// Mitsubishi GX Works2 project: Q系列PLC与BD4543V4241E通信例程   PLC: Q02/Q02H

PROGRAM MAIN
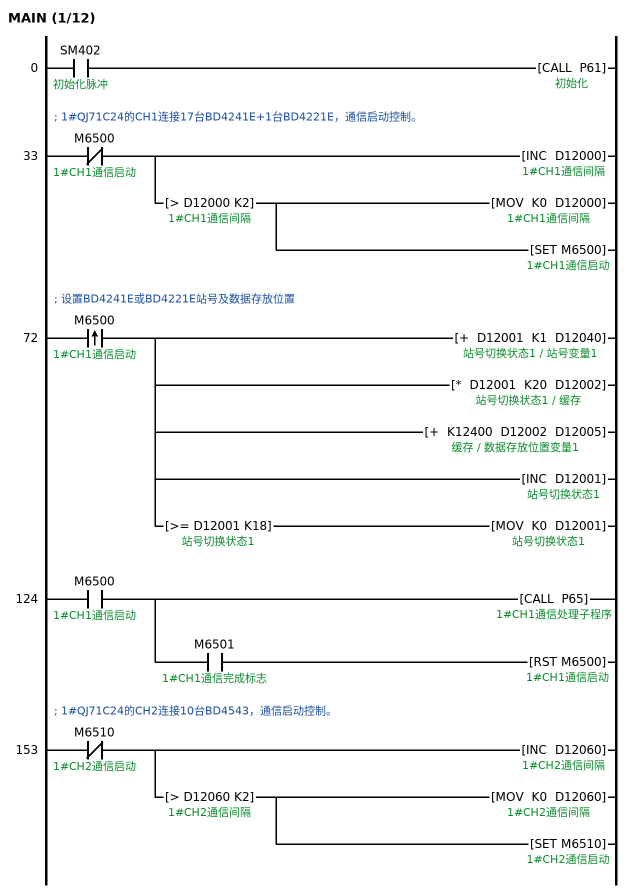
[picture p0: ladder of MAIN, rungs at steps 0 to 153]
0     LD      SM402  ; 初始化脉冲
      CALL    P61  ; 初始化
; 1#QJ71C24的CH1连接17台BD4241E+1台BD4221E，通信启动控制。
33    LDI     M6500  ; 1#CH1通信启动
      INC     D12000  ; 1#CH1通信间隔
      AND>    D12000 K2  ; 1#CH1通信间隔
      MOV     K0 D12000
      SET     M6500  ; 1#CH1通信启动
; 设置BD4241E或BD4221E站号及数据存放位置
72    LDP     M6500  ; 1#CH1通信启动
      +       D12001 K1 D12040  ; 站号切换状态1 / 站号变量1
        [note] 参与通讯站号
      *       D12001 K20 D12002  ; 缓存
      +       K12400 D12002 D12005  ; 数据存放位置变量1
        [note] 数据存放开始位置（D号）
      INC     D12001
      AND>=   D12001 K18  ; 站号切换状态1
      MOV     K0 D12001
        [note] BD4241/21模块个数
124   LD      M6500  ; 1#CH1通信启动
      CALL    P65  ; 1#CH1通信处理子程序
      AND     M6501  ; 1#CH1通信完成标志
      RST     M6500  ; 1#CH1通信启动
; 1#QJ71C24的CH2连接10台BD4543，通信启动控制。
153   LDI     M6510  ; 1#CH2通信启动
      INC     D12060  ; 1#CH2通信间隔
      AND>    D12060 K2  ; 1#CH2通信间隔
      MOV     K0 D12060
      SET     M6510  ; 1#CH2通信启动
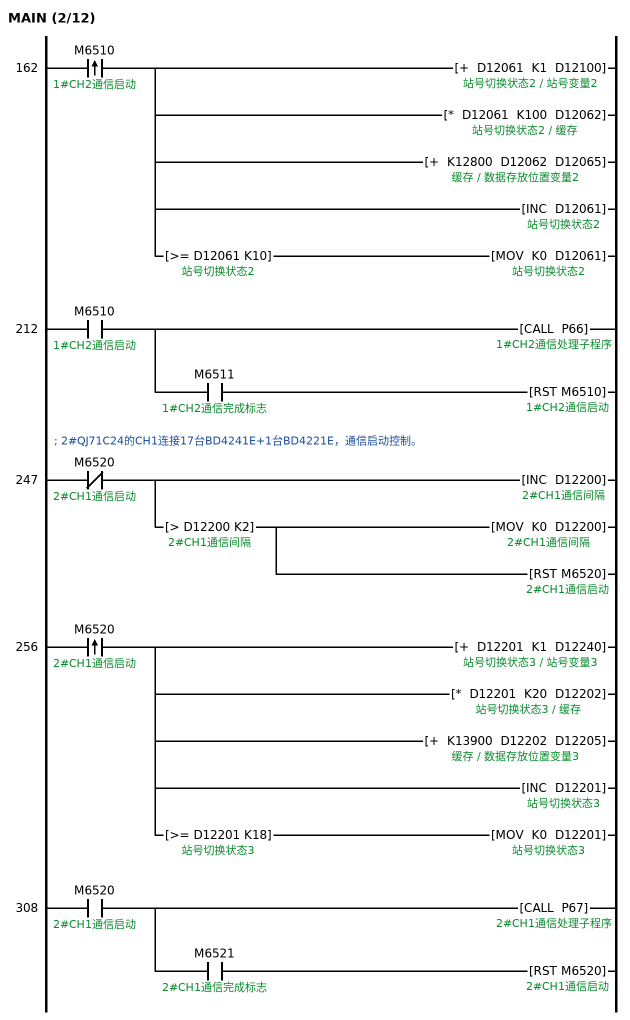
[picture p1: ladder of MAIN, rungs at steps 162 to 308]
162   LDP     M6510  ; 1#CH2通信启动
      +       D12061 K1 D12100  ; 站号切换状态2 / 站号变量2
        [note] 参与通讯站号
      *       D12061 K100 D12062  ; 缓存
      +       K12800 D12062 D12065  ; 数据存放位置变量2
        [note] 数据存放开始位置（D号）
      INC     D12061
      AND>=   D12061 K10  ; 站号切换状态2
      MOV     K0 D12061
        [note] BD4543模块个数
212   LD      M6510  ; 1#CH2通信启动
      CALL    P66  ; 1#CH2通信处理子程序
      AND     M6511  ; 1#CH2通信完成标志
      RST     M6510  ; 1#CH2通信启动
; 2#QJ71C24的CH1连接17台BD4241E+1台BD4221E，通信启动控制。
247   LDI     M6520  ; 2#CH1通信启动
      INC     D12200  ; 2#CH1通信间隔
      AND>    D12200 K2  ; 2#CH1通信间隔
      MOV     K0 D12200
      RST     M6520  ; 2#CH1通信启动
256   LDP     M6520  ; 2#CH1通信启动
      +       D12201 K1 D12240  ; 站号切换状态3 / 站号变量3
        [note] 参与通讯站号
      *       D12201 K20 D12202  ; 缓存
      +       K13900 D12202 D12205  ; 数据存放位置变量3
        [note] 数据存放开始位置（D号）
      INC     D12201
      AND>=   D12201 K18  ; 站号切换状态3
      MOV     K0 D12201
        [note] BD4241/21模块个数
308   LD      M6520  ; 2#CH1通信启动
      CALL    P67  ; 2#CH1通信处理子程序
      AND     M6521  ; 2#CH1通信完成标志
      RST     M6520  ; 2#CH1通信启动
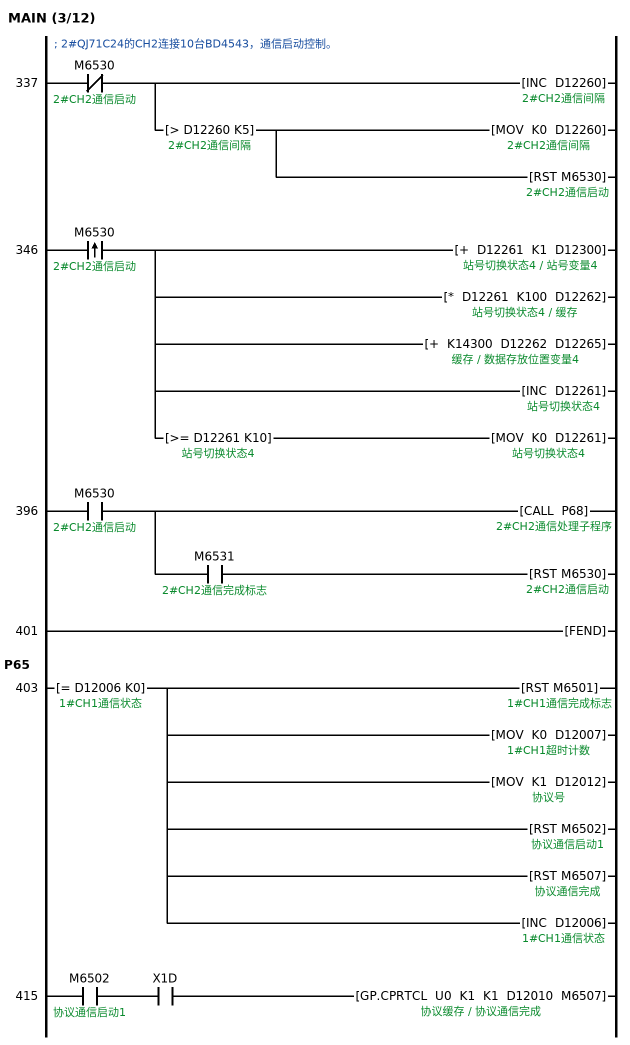
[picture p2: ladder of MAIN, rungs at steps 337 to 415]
; 2#QJ71C24的CH2连接10台BD4543，通信启动控制。
337   LDI     M6530  ; 2#CH2通信启动
      INC     D12260  ; 2#CH2通信间隔
      AND>    D12260 K5  ; 2#CH2通信间隔
      MOV     K0 D12260
      RST     M6530  ; 2#CH2通信启动
346   LDP     M6530  ; 2#CH2通信启动
      +       D12261 K1 D12300  ; 站号切换状态4 / 站号变量4
        [note] 参与通讯站号
      *       D12261 K100 D12262  ; 缓存
      +       K14300 D12262 D12265  ; 数据存放位置变量4
        [note] 数据存放开始位置（D号）
      INC     D12261
      AND>=   D12261 K10  ; 站号切换状态4
      MOV     K0 D12261
        [note] BD4543模块个数
396   LD      M6530  ; 2#CH2通信启动
      CALL    P68  ; 2#CH2通信处理子程序
      AND     M6531  ; 2#CH2通信完成标志
      RST     M6530  ; 2#CH2通信启动
401   FEND
      P65
403   LD=     D12006 K0  ; 1#CH1通信状态
      RST     M6501  ; 1#CH1通信完成标志
      MOV     K0 D12007  ; 1#CH1超时计数
      MOV     K1 D12012  ; 协议号
      RST     M6502  ; 协议通信启动1
      RST     M6507  ; 协议通信完成
      INC     D12006
415   LD      M6502  ; 协议通信启动1
      AND     X1D
      GP.CPRTCL U0 K1 K1 D12010 M6507  ; 协议缓存
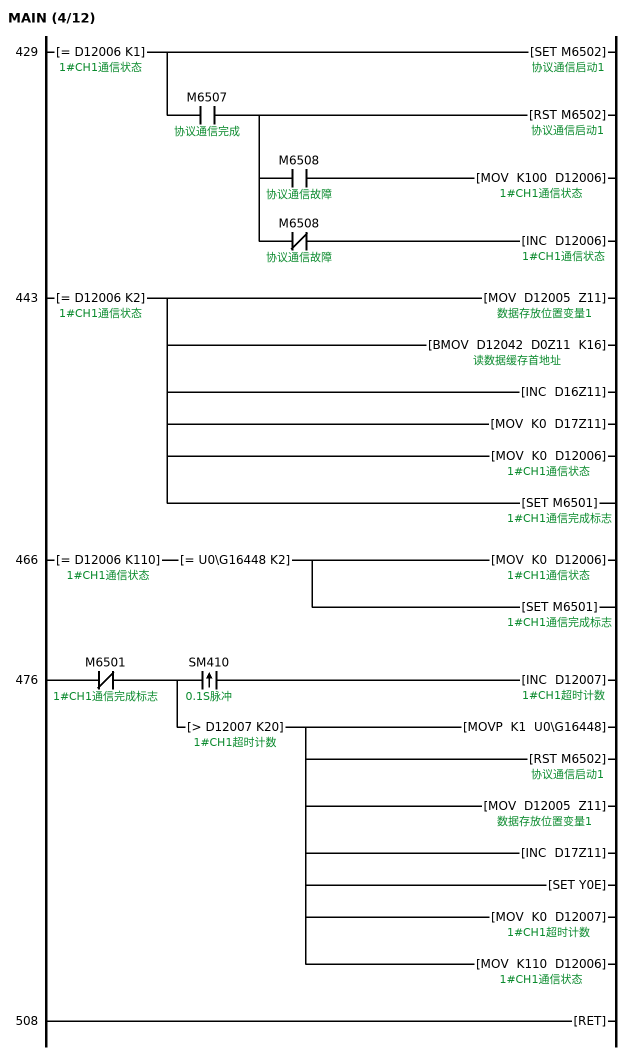
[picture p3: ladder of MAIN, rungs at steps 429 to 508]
429   LD=     D12006 K1  ; 1#CH1通信状态
      SET     M6502  ; 协议通信启动1
      AND     M6507  ; 协议通信完成
      RST     M6502  ; 协议通信启动1
      MPS
      AND     M6508  ; 协议通信故障
      MOV     K100 D12006
      MPP
      ANI     M6508  ; 协议通信故障
      INC     D12006
443   LD=     D12006 K2  ; 1#CH1通信状态
      MOV     D12005 Z11
      BMOV    D12042 D0Z11 K16  ; 读数据缓存首地址
      INC     D16Z11
        [note] 通信计数
      MOV     K0 D17Z11
      MOV     K0 D12006
      SET     M6501  ; 1#CH1通信完成标志
466   LD=     D12006 K110  ; 1#CH1通信状态
      AND=    U0\G16448 K2
      MOV     K0 D12006
      SET     M6501  ; 1#CH1通信完成标志
476   LDI     M6501  ; 1#CH1通信完成标志
      MPS
      ANDP    SM410  ; 0.1S脉冲
      INC     D12007
      MPP
      AND>    D12007 K20  ; 1#CH1超时计数
      MOVP    K1 U0\G16448
      RST     M6502  ; 协议通信启动1
      MOV     D12005 Z11
      INC     D17Z11
        [note] 通信错误计数
      SET     Y0E
      MOV     K0 D12007
      MOV     K110 D12006
508   RET
      P66
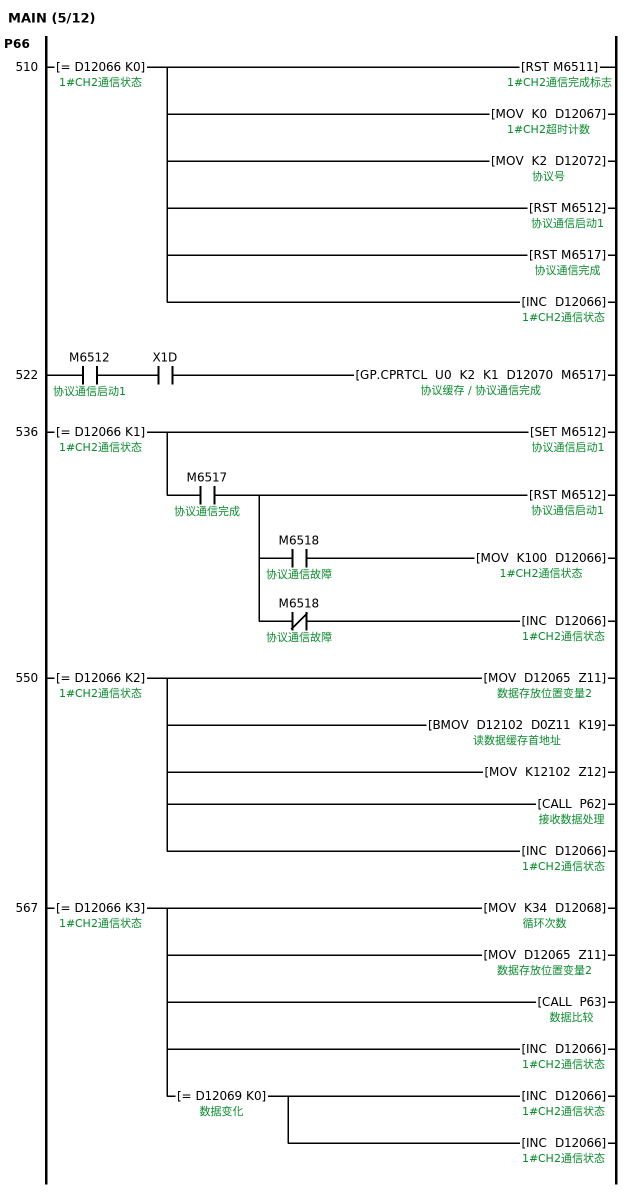
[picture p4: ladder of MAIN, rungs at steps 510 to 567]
510   LD=     D12066 K0  ; 1#CH2通信状态
      RST     M6511  ; 1#CH2通信完成标志
      MOV     K0 D12067  ; 1#CH2超时计数
      MOV     K2 D12072  ; 协议号
      RST     M6512  ; 协议通信启动1
      RST     M6517  ; 协议通信完成
      INC     D12066
522   LD      M6512  ; 协议通信启动1
      AND     X1D
      GP.CPRTCL U0 K2 K1 D12070 M6517  ; 协议缓存
536   LD=     D12066 K1  ; 1#CH2通信状态
      SET     M6512  ; 协议通信启动1
      AND     M6517  ; 协议通信完成
      RST     M6512  ; 协议通信启动1
      MPS
      AND     M6518  ; 协议通信故障
      MOV     K100 D12066
      MPP
      ANI     M6518  ; 协议通信故障
      INC     D12066
550   LD=     D12066 K2  ; 1#CH2通信状态
      MOV     D12065 Z11
      BMOV    D12102 D0Z11 K19  ; 读数据缓存首地址
      MOV     K12102 Z12
      CALL    P62  ; 接收数据处理
      INC     D12066
567   LD=     D12066 K3  ; 1#CH2通信状态
      MOV     K34 D12068  ; 循环次数
      MOV     D12065 Z11
      CALL    P63  ; 数据比较
      INC     D12066
      AND=    D12069 K0  ; 数据变化
      INC     D12066
      INC     D12066
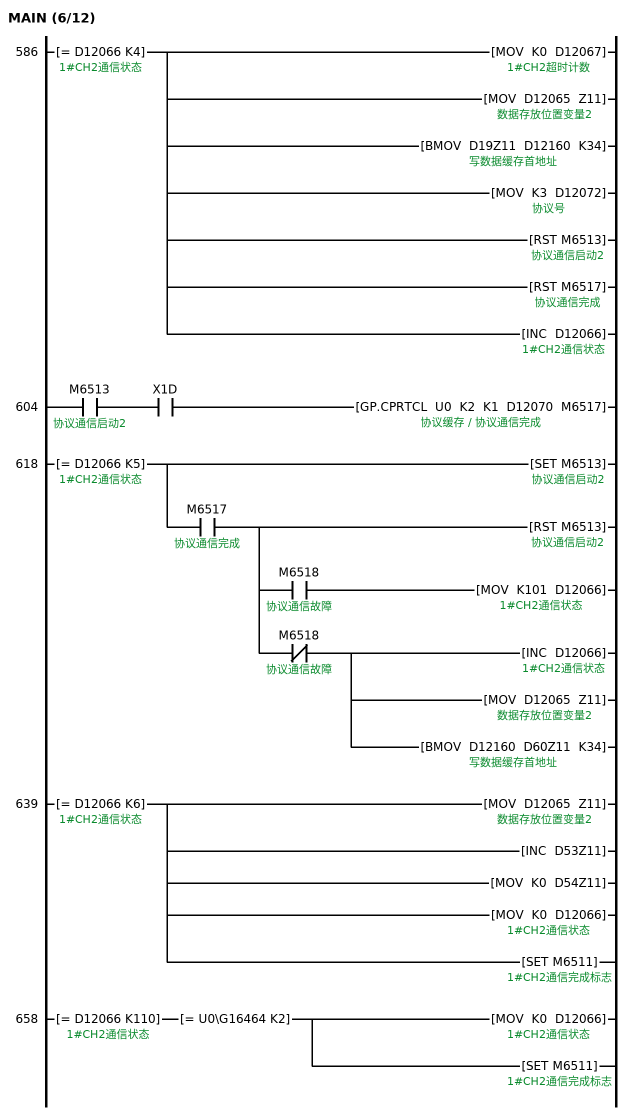
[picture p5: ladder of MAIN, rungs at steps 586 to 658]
586   LD=     D12066 K4  ; 1#CH2通信状态
      MOV     K0 D12067
      MOV     D12065 Z11
      BMOV    D19Z11 D12160 K34  ; 写数据缓存首地址
      MOV     K3 D12072
      RST     M6513  ; 协议通信启动2
      RST     M6517  ; 协议通信完成
      INC     D12066
604   LD      M6513  ; 协议通信启动2
      AND     X1D
      GP.CPRTCL U0 K2 K1 D12070 M6517
618   LD=     D12066 K5  ; 1#CH2通信状态
      SET     M6513  ; 协议通信启动2
      AND     M6517  ; 协议通信完成
      RST     M6513  ; 协议通信启动2
      MPS
      AND     M6518  ; 协议通信故障
      MOV     K101 D12066
      MPP
      ANI     M6518  ; 协议通信故障
      INC     D12066
      MOV     D12065 Z11
      BMOV    D12160 D60Z11 K34
639   LD=     D12066 K6  ; 1#CH2通信状态
      MOV     D12065 Z11
      INC     D53Z11
        [note] 通信计数
      MOV     K0 D54Z11
      MOV     K0 D12066
      SET     M6511  ; 1#CH2通信完成标志
658   LD=     D12066 K110  ; 1#CH2通信状态
      AND=    U0\G16464 K2
      MOV     K0 D12066
      SET     M6511  ; 1#CH2通信完成标志
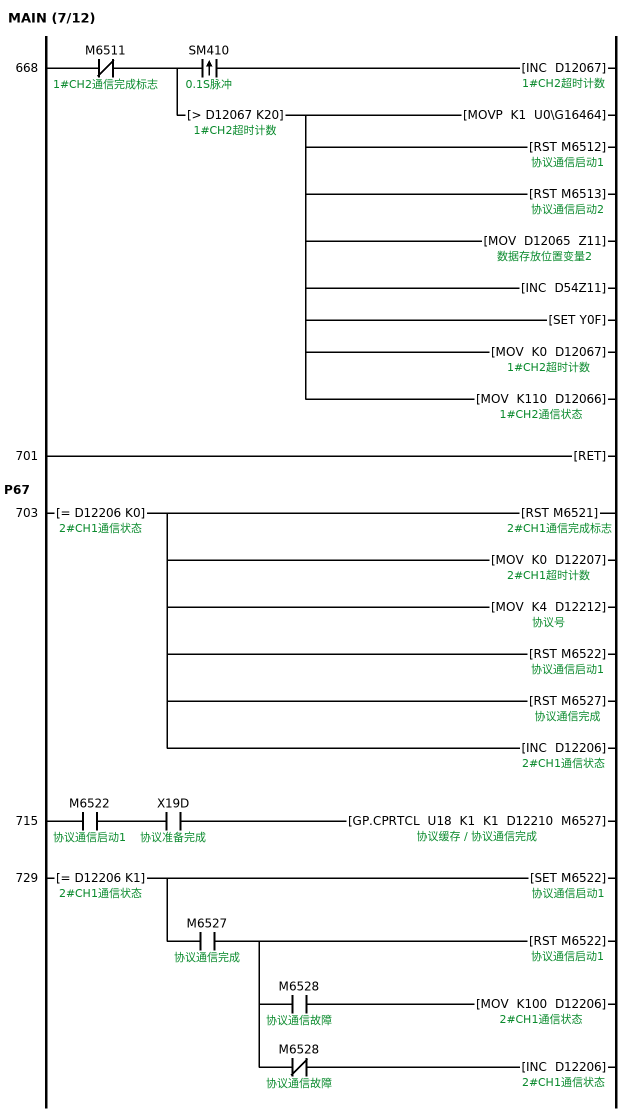
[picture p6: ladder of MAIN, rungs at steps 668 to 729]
668   LDI     M6511  ; 1#CH2通信完成标志
      MPS
      ANDP    SM410  ; 0.1S脉冲
      INC     D12067
      MPP
      AND>    D12067 K20  ; 1#CH2超时计数
      MOVP    K1 U0\G16464
      RST     M6512  ; 协议通信启动1
      RST     M6513  ; 协议通信启动2
      MOV     D12065 Z11
      INC     D54Z11
        [note] 通信错误计数
      SET     Y0F
      MOV     K0 D12067
      MOV     K110 D12066
701   RET
      P67
703   LD=     D12206 K0  ; 2#CH1通信状态
      RST     M6521  ; 2#CH1通信完成标志
      MOV     K0 D12207  ; 2#CH1超时计数
      MOV     K4 D12212  ; 协议号
      RST     M6522  ; 协议通信启动1
      RST     M6527  ; 协议通信完成
      INC     D12206
715   LD      M6522  ; 协议通信启动1
      AND     X19D  ; 协议准备完成
      GP.CPRTCL U18 K1 K1 D12210 M6527  ; 协议缓存
729   LD=     D12206 K1  ; 2#CH1通信状态
      SET     M6522  ; 协议通信启动1
      AND     M6527  ; 协议通信完成
      RST     M6522  ; 协议通信启动1
      MPS
      AND     M6528  ; 协议通信故障
      MOV     K100 D12206
      MPP
      ANI     M6528  ; 协议通信故障
      INC     D12206
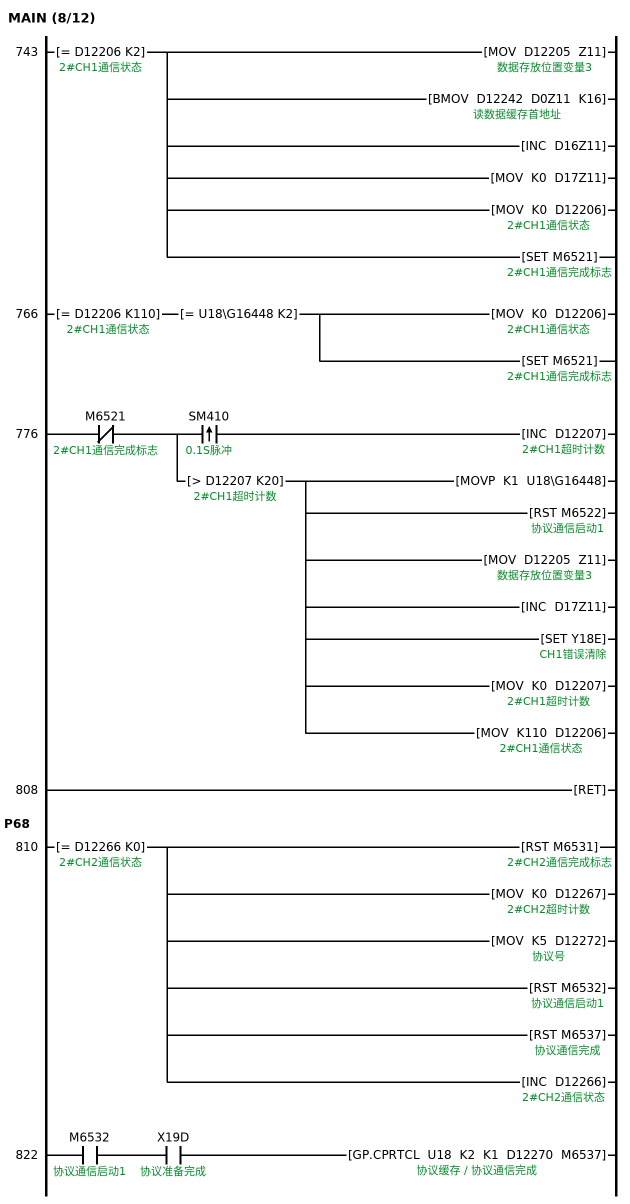
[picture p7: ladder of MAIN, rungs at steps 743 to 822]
743   LD=     D12206 K2  ; 2#CH1通信状态
      MOV     D12205 Z11
      BMOV    D12242 D0Z11 K16  ; 读数据缓存首地址
      INC     D16Z11
        [note] 通信计数
      MOV     K0 D17Z11
      MOV     K0 D12206
      SET     M6521  ; 2#CH1通信完成标志
766   LD=     D12206 K110  ; 2#CH1通信状态
      AND=    U18\G16448 K2
      MOV     K0 D12206
      SET     M6521  ; 2#CH1通信完成标志
776   LDI     M6521  ; 2#CH1通信完成标志
      MPS
      ANDP    SM410  ; 0.1S脉冲
      INC     D12207
      MPP
      AND>    D12207 K20  ; 2#CH1超时计数
      MOVP    K1 U18\G16448
      RST     M6522  ; 协议通信启动1
      MOV     D12205 Z11
      INC     D17Z11
        [note] 通信错误计数
      SET     Y18E  ; CH1错误清除
      MOV     K0 D12207
      MOV     K110 D12206
808   RET
      P68
810   LD=     D12266 K0  ; 2#CH2通信状态
      RST     M6531  ; 2#CH2通信完成标志
      MOV     K0 D12267  ; 2#CH2超时计数
      MOV     K5 D12272  ; 协议号
      RST     M6532  ; 协议通信启动1
      RST     M6537  ; 协议通信完成
      INC     D12266
822   LD      M6532  ; 协议通信启动1
      AND     X19D  ; 协议准备完成
      GP.CPRTCL U18 K2 K1 D12270 M6537  ; 协议缓存
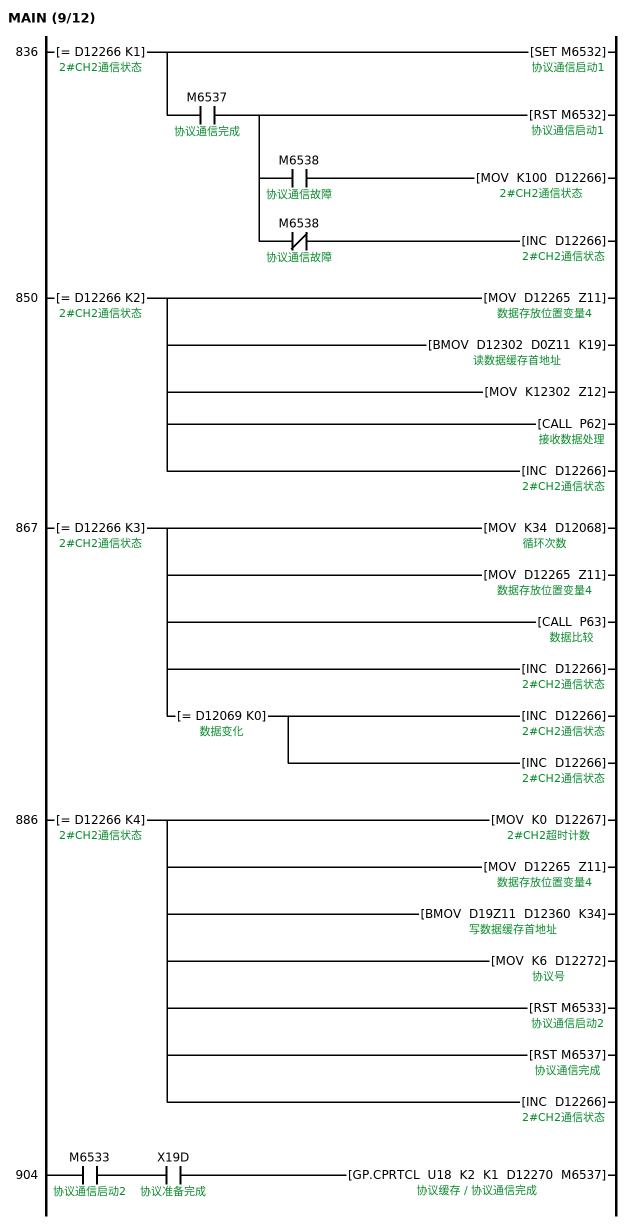
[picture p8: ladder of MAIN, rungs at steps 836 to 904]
836   LD=     D12266 K1  ; 2#CH2通信状态
      SET     M6532  ; 协议通信启动1
      AND     M6537  ; 协议通信完成
      RST     M6532  ; 协议通信启动1
      MPS
      AND     M6538  ; 协议通信故障
      MOV     K100 D12266
      MPP
      ANI     M6538  ; 协议通信故障
      INC     D12266
850   LD=     D12266 K2  ; 2#CH2通信状态
      MOV     D12265 Z11
      BMOV    D12302 D0Z11 K19  ; 读数据缓存首地址
      MOV     K12302 Z12
      CALL    P62
      INC     D12266
867   LD=     D12266 K3  ; 2#CH2通信状态
      MOV     K34 D12068
      MOV     D12265 Z11
      CALL    P63
      INC     D12266
      AND=    D12069 K0  ; 数据变化
      INC     D12266
      INC     D12266
886   LD=     D12266 K4  ; 2#CH2通信状态
      MOV     K0 D12267
      MOV     D12265 Z11
      BMOV    D19Z11 D12360 K34  ; 写数据缓存首地址
      MOV     K6 D12272
      RST     M6533  ; 协议通信启动2
      RST     M6537  ; 协议通信完成
      INC     D12266
904   LD      M6533  ; 协议通信启动2
      AND     X19D  ; 协议准备完成
      GP.CPRTCL U18 K2 K1 D12270 M6537
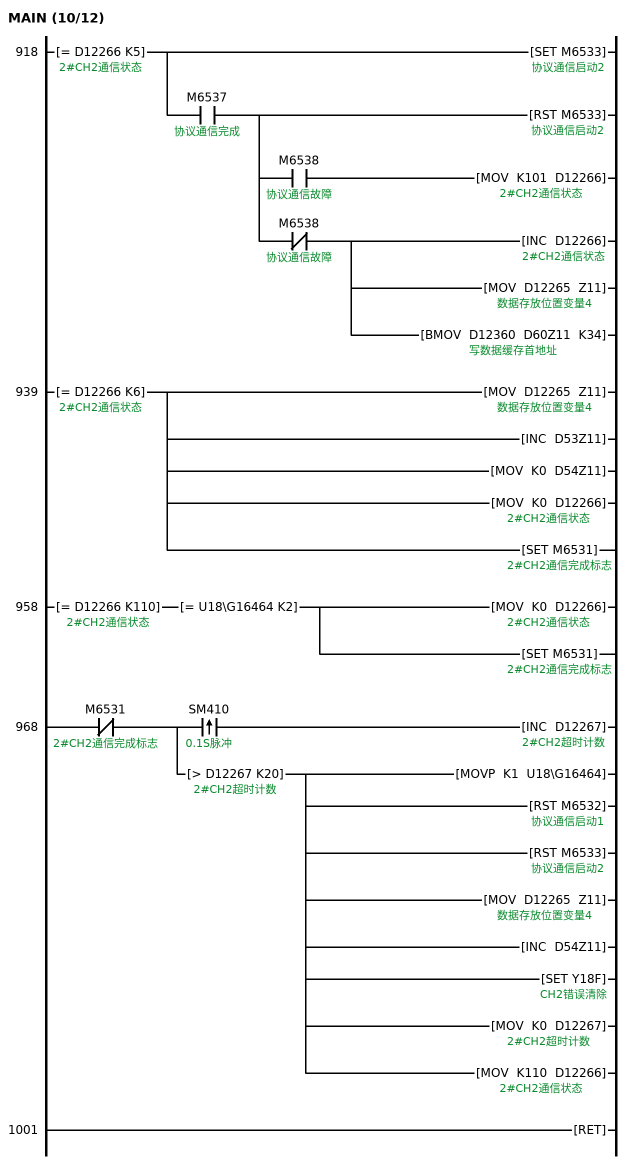
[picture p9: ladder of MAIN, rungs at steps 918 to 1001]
918   LD=     D12266 K5  ; 2#CH2通信状态
      SET     M6533  ; 协议通信启动2
      AND     M6537  ; 协议通信完成
      RST     M6533  ; 协议通信启动2
      MPS
      AND     M6538  ; 协议通信故障
      MOV     K101 D12266
      MPP
      ANI     M6538  ; 协议通信故障
      INC     D12266
      MOV     D12265 Z11
      BMOV    D12360 D60Z11 K34
939   LD=     D12266 K6  ; 2#CH2通信状态
      MOV     D12265 Z11
      INC     D53Z11
        [note] 通信计数
      MOV     K0 D54Z11
      MOV     K0 D12266
      SET     M6531  ; 2#CH2通信完成标志
958   LD=     D12266 K110  ; 2#CH2通信状态
      AND=    U18\G16464 K2
      MOV     K0 D12266
      SET     M6531  ; 2#CH2通信完成标志
968   LDI     M6531  ; 2#CH2通信完成标志
      MPS
      ANDP    SM410  ; 0.1S脉冲
      INC     D12267
      MPP
      AND>    D12267 K20  ; 2#CH2超时计数
      MOVP    K1 U18\G16464
      RST     M6532  ; 协议通信启动1
      RST     M6533  ; 协议通信启动2
      MOV     D12265 Z11
      INC     D54Z11
        [note] 通信错误计数
      SET     Y18F  ; CH2错误清除
      MOV     K0 D12267
      MOV     K110 D12266
1001  RET
      P63
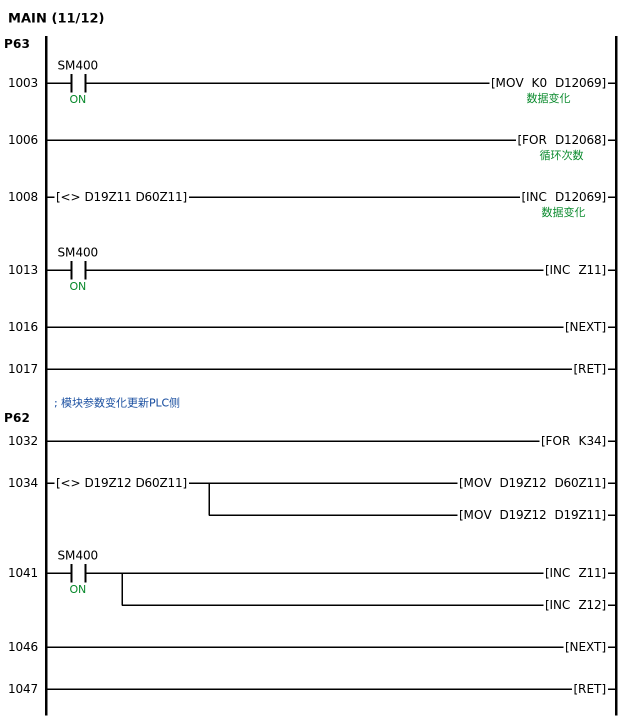
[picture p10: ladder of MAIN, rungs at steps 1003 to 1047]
1003  LD      SM400  ; ON
      MOV     K0 D12069
1006  FOR     D12068
1008  LD<>    D19Z11 D60Z11
      INC     D12069
1013  LD      SM400  ; ON
      INC     Z11
1016  NEXT
1017  RET
; 模块参数变化更新PLC侧
      P62
1032  FOR     K34
1034  LD<>    D19Z12 D60Z11
      MOV     D19Z12 D60Z11
      MOV     D19Z12 D19Z11
1041  LD      SM400  ; ON
      INC     Z11
      INC     Z12
1046  NEXT
1047  RET
      P61
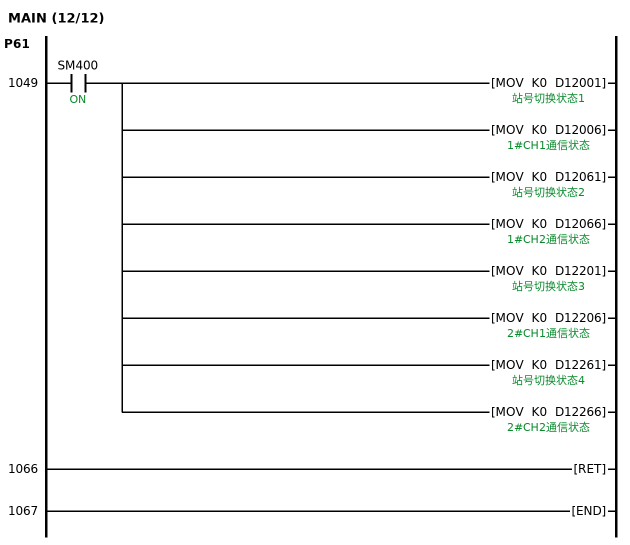
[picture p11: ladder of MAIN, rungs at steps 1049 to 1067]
1049  LD      SM400  ; ON
      MOV     K0 D12001
      MOV     K0 D12006
      MOV     K0 D12061
      MOV     K0 D12066
      MOV     K0 D12201
      MOV     K0 D12206
      MOV     K0 D12261
      MOV     K0 D12266
1066  RET
1067  END
END_PROGRAM

// device comments not shown above
X5D  ; 协议准备完成
D48  ; 通信故障计数
D12041  ; 站号缓存1
D12101  ; 站号缓存2
D12241  ; 站号缓存3
D12301  ; 站号缓存4
Y4E  ; CH1错误清除
Y4F  ; CH2错误清除
